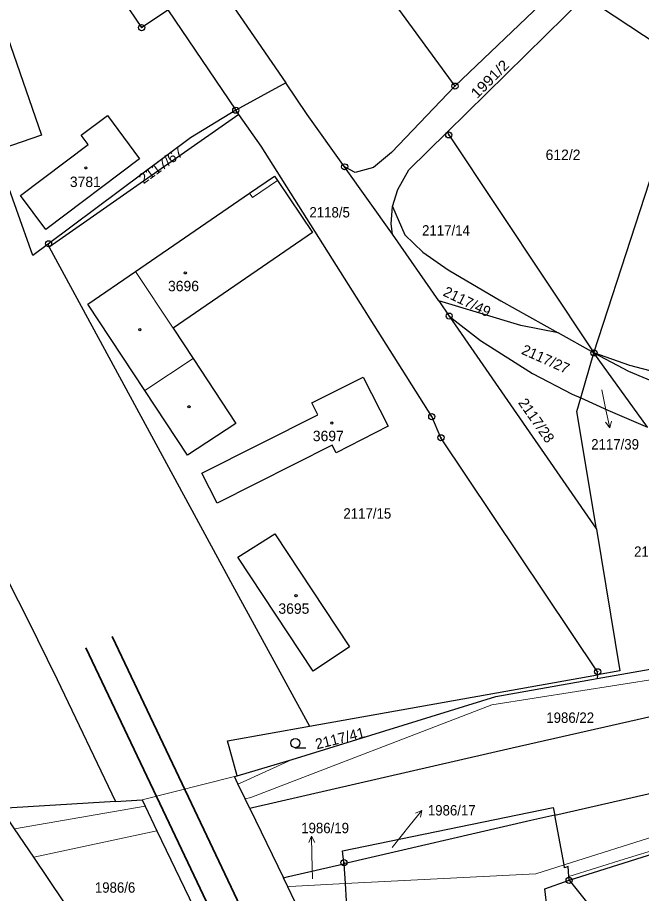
# Model space of a CAD drawing. Extents: x -679733 to -673243, y -1075091 to -1066557.
# Drawn here: x -675852.7 to -675750.8, y -1071520.5 to -1071377.5 of the extents above; entities that cross this region are included whole.
import ezdxf
from ezdxf.enums import TextEntityAlignment as Align

# ---------------------------------------------------------------- set-up
doc = ezdxf.new("R2010")
doc.units = 0
doc.header["$LTSCALE"] = 0.68
for name, color, linetype, lineweight in [('1', 7, 'Continuous', 25), ('3', 7, 'Continuous', 25), ('4', 7, 'Continuous', 13), ('5', 7, 'Continuous', 25), ('6', 7, 'Continuous', 35), ('7', 7, 'Continuous', 13), ('8', 7, 'Continuous', 25)]:
    doc.layers.add(name, color=color, linetype=linetype, lineweight=lineweight)
doc.layers.add('2', color=7, linetype='Continuous')

msp = doc.modelspace()

# ---------------------------------------------------------------- linework, layer by layer
at = {"layer": '1'}
for p, q in [((-675781.29, -1071388.68), (-675764, -1071372.14)), ((-675828.15, -1071376.24), (-675817.07, -1071392.61)), ((-675808.93, -1071388.15), (-675817.07, -1071392.61)), ((-675816.59, -1071393.3), (-675817.07, -1071392.61)), ((-675816.59, -1071393.3), (-675847.52, -1071414.95)), ((-675791.49, -1071412.85), (-675799.31, -1071401.85)), ((-675783.94, -1071423.72), (-675791.49, -1071412.85)), ((-675847.52, -1071414.95), (-675847.63, -1071414.41)), ((-675783.94, -1071423.72), (-675782.24, -1071426.22)), ((-675782.24, -1071426.22), (-675758.21, -1071461.03)), ((-675758.6, -1071432.23), (-675764.46, -1071428.95)), ((-675805.04, -1071493.15), (-675758.03, -1071484.77)), ((-675836.69, -1071505.46), (-675855.42, -1071506.6)), ((-675762.66, -1071518.33), (-675759.37, -1071522.39))]:
    msp.add_line(p, q, dxfattribs=at)
for points in [[(-675854.82, -1071284.95), (-675848.63, -1071294.37), (-675837.94, -1071309.28), (-675816.23, -1071340.27), (-675801.2, -1071361.46), (-675781.29, -1071388.68)], [(-675847.63, -1071414.41), (-675850.21, -1071416.33), (-675866.27, -1071371.22), (-675873.33, -1071374.74), (-675886.25, -1071340.1), (-675896.49, -1071301.05), (-675888.9, -1071295.99), (-675877.65, -1071312.62), (-675832.44, -1071379.13), (-675828.15, -1071376.24)], [(-675867.83, -1071302.12), (-675854.84, -1071321.36), (-675808.93, -1071388.15)], [(-675981.32, -1071321.28), (-675979.71, -1071320.17), (-675958.96, -1071344.08), (-675942.19, -1071358.69), (-675925.65, -1071376.26), (-675903.8, -1071399.59), (-675900.1, -1071402.8), (-675886.01, -1071422.07), (-675873.55, -1071440.05), (-675863.47, -1071455.5), (-675854.14, -1071469.73), (-675851.06, -1071475.72), (-675846.24, -1071485.53), (-675836.69, -1071505.46)], [(-675743.35, -1071385.17), (-675760.12, -1071374.06), (-675782.59, -1071396.19)], [(-675799.31, -1071401.85), (-675805.4, -1071393.29), (-675808.93, -1071388.15)], [(-675781.29, -1071388.68), (-675791.67, -1071399.52), (-675794.62, -1071401.98), (-675797.61, -1071402.8), (-675799.31, -1071401.85)], [(-675782.59, -1071396.19), (-675782.3, -1071396.64), (-675758.6, -1071432.23), (-675745.03, -1071390.44)], [(-675817.07, -1071392.61), (-675824.45, -1071397.14), (-675847.63, -1071414.41)], [(-675758.03, -1071484.77), (-675758.01, -1071484.29), (-675783.58, -1071446.08), (-675785.08, -1071442.63), (-675812.93, -1071398.49), (-675816.59, -1071393.3)], [(-675791.49, -1071408.32), (-675790.61, -1071405.53), (-675788.84, -1071402.35), (-675782.59, -1071396.19)], [(-675791.49, -1071412.85), (-675791.72, -1071411.17), (-675791.49, -1071408.32)], [(-675791.49, -1071408.32), (-675789.47, -1071412.94), (-675786.56, -1071415.8), (-675782.4, -1071418.64), (-675773.78, -1071423.73), (-675764.46, -1071428.95)], [(-675847.52, -1071414.95), (-675817.61, -1071470.14), (-675805.04, -1071493.15)], [(-675696.11, -1071420.65), (-675710.01, -1071445.5), (-675752.77, -1071434.27), (-675758.6, -1071432.23)], [(-675764.46, -1071428.95), (-675770.52, -1071427.75), (-675783.94, -1071423.72)], [(-675782.24, -1071426.22), (-675777.14, -1071430.21), (-675768.65, -1071435.57), (-675762.15, -1071438.95), (-675760.77, -1071439.57), (-675758.6, -1071432.23)], [(-675760.77, -1071439.57), (-675756.32, -1071441.58), (-675749.84, -1071444.33), (-675758.6, -1071432.23)], [(-675758.6, -1071432.23), (-675752.95, -1071435.22), (-675730.97, -1071444.42), (-675725.97, -1071446.45), (-675719.18, -1071448.79), (-675712.12, -1071450.99), (-675690.33, -1071455.9), (-675685.55, -1071451.33)], [(-675758.21, -1071461.03), (-675761.42, -1071441.77), (-675760.77, -1071439.57)], [(-675765.01, -1071507.69), (-675720.68, -1071497.6), (-675701.7, -1071493), (-675681.33, -1071488.01), (-675670.56, -1071485.93), (-675653.21, -1071481.97), (-675639.53, -1071478.73), (-675629.19, -1071475.57), (-675618.73, -1071471.91), (-675604.22, -1071466.89), (-675596.96, -1071465.22), (-675589.14, -1071463.42), (-675580.81, -1071461.62), (-675571.9, -1071459.71), (-675564.88, -1071458.18), (-675556.76, -1071456.48), (-675552.97, -1071456.9), (-675552.7, -1071457.95)], [(-675762.66, -1071518.33), (-675718.98, -1071504.52), (-675696.21, -1071498.47), (-675686.03, -1071495.76), (-675667.73, -1071490.69), (-675659.08, -1071487.52), (-675634.37, -1071480.95), (-675603.24, -1071472.27), (-675600.58, -1071471.53), (-675591.26, -1071468.63), (-675587.81, -1071467.56), (-675579.07, -1071464.85), (-675557.23, -1071459.13), (-675552.7, -1071457.95)], [(-675758.21, -1071461.03), (-675754.37, -1071484.11), (-675758.03, -1071484.77)], [(-675692.82, -1071478.48), (-675722.98, -1071485.64), (-675771.94, -1071496.74), (-675814.37, -1071506.52), (-675814.77, -1071506.62), (-675809.31, -1071517.91)], [(-675758.03, -1071484.77), (-675758.07, -1071485.41), (-675745.4, -1071483.17)], [(-675816.83, -1071501.25), (-675807.89, -1071498.61), (-675774.62, -1071488.33), (-675758.07, -1071485.41)], [(-675816.83, -1071501.25), (-675818.43, -1071495.54), (-675805.04, -1071493.15)], [(-675814.77, -1071506.62), (-675815.54, -1071505.04), (-675816.72, -1071502.59), (-675817.3, -1071501.39), (-675816.83, -1071501.25)], [(-675836.69, -1071505.46), (-675832.38, -1071505.2), (-675831.88, -1071506.24), (-675829.96, -1071510.26), (-675824.71, -1071521.21), (-675824.03, -1071522.63), (-675822.74, -1071525.31), (-675822, -1071526.86), (-675822.98, -1071527.31)], [(-675837.15, -1071533.74), (-675838.99, -1071531.01), (-675840.42, -1071528.88), (-675842.72, -1071525.48), (-675850.05, -1071514.58), (-675853.19, -1071509.92), (-675855.42, -1071506.6)], [(-675799.42, -1071515.63), (-675799.43, -1071515.45), (-675799.65, -1071513.5), (-675765.24, -1071506.45), (-675765.01, -1071507.69)], [(-675765.01, -1071507.69), (-675768.92, -1071508.58), (-675799.42, -1071515.63)], [(-675762.66, -1071518.33), (-675762.7, -1071517.7), (-675762.79, -1071516.09), (-675763.39, -1071516.29), (-675763.48, -1071515.8), (-675765.01, -1071507.69)], [(-675809.31, -1071517.91), (-675808.48, -1071517.73), (-675799.42, -1071515.63)], [(-675799.42, -1071515.63), (-675799.23, -1071518.87), (-675799.06, -1071521.66), (-675798.6, -1071523.24)], [(-675804.16, -1071523.03), (-675806.88, -1071522.93), (-675807.43, -1071521.79), (-675808.59, -1071519.4), (-675809.31, -1071517.91)], [(-675781.27, -1071526.04), (-675766.22, -1071523), (-675766.64, -1071519.74), (-675762.66, -1071518.33)]]:
    msp.add_lwpolyline(points, dxfattribs=at)
for points in [[(-675855.35, -1071377.62), (-675848.77, -1071396.69), (-675855.29, -1071398.93), (-675861.88, -1071379.88)], [(-675848.1, -1071412.06), (-675852.24, -1071406.55), (-675841.18, -1071398.21), (-675842.32, -1071396.7), (-675838, -1071393.46), (-675832.78, -1071400.55)], [(-675810.74, -1071403.35), (-675810.26, -1071404.06), (-675804.54, -1071412.58), (-675827.32, -1071428.17), (-675824.05, -1071433.13), (-675817.07, -1071443.74), (-675824.95, -1071448.94), (-675831.94, -1071438.34), (-675841.22, -1071424.28), (-675833.42, -1071418.93), (-675814.82, -1071406.15)], [(-675801.36, -1071447.28), (-675820.14, -1071456.75), (-675822.61, -1071451.86), (-675803.7, -1071442.32), (-675804.67, -1071440.38), (-675796.3, -1071436.17), (-675792.22, -1071444.17), (-675800.69, -1071448.57)], [(-675816.74, -1071465.56), (-675810.68, -1071461.78), (-675798.5, -1071480.23), (-675804.46, -1071484.17)]]:
    msp.add_lwpolyline(points, close=True, dxfattribs=at)
at = {"layer": '3'}
msp.add_line((-675807.363, -1071496.68), (-675805.613, -1071496.68), dxfattribs=at)
msp.add_circle((-675807.3629, -1071495.9298), 0.75, dxfattribs=at)
at = {"layer": '4'}
for p, q in [((-675814.34, -1071406.86), (-675810.26, -1071404.06)), ((-675814.82, -1071406.15), (-675814.34, -1071406.86)), ((-675827.32, -1071428.17), (-675833.42, -1071418.93)), ((-675831.94, -1071438.34), (-675824.05, -1071433.13)), ((-675775.26, -1071489.68), (-675723.75, -1071481.57)), ((-675814.63, -1071504.8), (-675775.26, -1071489.68)), ((-675816.45, -1071502.52), (-675807.89, -1071498.61)), ((-675832.38, -1071505.2), (-675817.3, -1071501.39)), ((-675816.72, -1071502.59), (-675816.45, -1071502.52)), ((-675763.48, -1071515.8), (-675719.73, -1071501.99)), ((-675717.48, -1071503.73), (-675753.65, -1071514.87)), ((-675815.54, -1071505.04), (-675814.63, -1071504.8)), ((-675853.19, -1071509.92), (-675831.88, -1071506.24)), ((-675850.05, -1071514.58), (-675829.96, -1071510.26)), ((-675753.65, -1071514.87), (-675762.7, -1071517.7)), ((-675768.11, -1071517.26), (-675763.48, -1071515.8)), ((-675799.23, -1071518.87), (-675768.11, -1071517.26)), ((-675808.23, -1071519.33), (-675808.59, -1071519.4)), ((-675808.23, -1071519.33), (-675799.23, -1071518.87))]:
    msp.add_line(p, q, dxfattribs=at)
at = {"layer": '5'}
for centre in [(-675841.5568, -1071402.0292), (-675825.3168, -1071419.1692), (-675832.7268, -1071428.4392), (-675824.7168, -1071441.0192), (-675801.3968, -1071443.6792), (-675807.2368, -1071471.8592)]:
    msp.add_circle(centre, 0.175, dxfattribs=at)
at = {"layer": '6'}
for p, q in [((-675824.81, -1071504.74), (-675837.24, -1071478.53)), ((-675829.46, -1071505.81), (-675841.54, -1071480.37)), ((-675824.81, -1071504.74), (-675815.86, -1071523.61)), ((-675829.46, -1071505.81), (-675820.49, -1071524.71))]:
    msp.add_line(p, q, dxfattribs=at)
at = {"layer": '7'}
for p, q in [((-675756.016, -1071444.435), (-675755.734, -1071443.352)), ((-675786.701, -1071506.918), (-675787.721, -1071507.381)), ((-675804.692, -1071511.139), (-675805.176, -1071512.15))]:
    msp.add_line(p, q, dxfattribs=at)
for points in [[(-675757.32, -1071438.24), (-675756.64, -1071441.5), (-675756.016, -1071444.435), (-675756.714, -1071443.56)], [(-675791.54, -1071512.95), (-675788.59, -1071509.25), (-675786.701, -1071506.918), (-675786.943, -1071508.011)], [(-675804.57, -1071518.1), (-675804.64, -1071514.14), (-675804.692, -1071511.139), (-675804.174, -1071512.132)]]:
    msp.add_lwpolyline(points, dxfattribs=at)
at = {"layer": '8'}
for centre, radius in [((-675832.44, -1071379.1299), 0.5), ((-675832.44, -1071379.1299), 0.0303), ((-675781.29, -1071388.6799), 0.5), ((-675781.29, -1071388.6799), 0.0303), ((-675817.07, -1071392.6099), 0.5), ((-675817.07, -1071392.6099), 0.0303), ((-675782.3, -1071396.6399), 0.5), ((-675782.3, -1071396.6399), 0.0303), ((-675799.31, -1071401.8499), 0.5), ((-675799.31, -1071401.8499), 0.0303), ((-675847.63, -1071414.4099), 0.5), ((-675847.63, -1071414.4099), 0.0303), ((-675782.24, -1071426.2199), 0.5), ((-675782.24, -1071426.2199), 0.0303), ((-675758.6, -1071432.2299), 0.5), ((-675758.6, -1071432.2299), 0.0303), ((-675785.08, -1071442.6299), 0.5), ((-675785.08, -1071442.6299), 0.0303), ((-675783.58, -1071446.0799), 0.5), ((-675783.58, -1071446.0799), 0.0303), ((-675758.01, -1071484.2899), 0.5), ((-675758.01, -1071484.2899), 0.0303), ((-675799.43, -1071515.4499), 0.5), ((-675799.43, -1071515.4499), 0.0303), ((-675762.66, -1071518.3299), 0.5), ((-675762.66, -1071518.3299), 0.0303)]:
    msp.add_circle(centre, radius, dxfattribs=at)

# ---------------------------------------------------------------- texts
at = {"layer": '2', "width": 1.1}
msp.add_text('1991/2', height=1.7, rotation=45, dxfattribs=at).set_placement((-675774.9875, -1071388.1195), align=Align.CENTER)
at = {"layer": '2'}
msp.add_text('2117/67', height=1.7, rotation=36, dxfattribs=at).set_placement((-675832.13, -1071404.717))
for s, p in [('612/2', (-675763.65, -1071400.739)), ('3696', (-675825.61, -1071422.16)), ('3697', (-675801.97, -1071446.64)), ('3695', (-675807.59, -1071474.82))]:
    msp.add_text(s, height=1.7, dxfattribs=at).set_placement(p, align=Align.CENTER)
msp.add_text('3781', height=1.7, dxfattribs=at).set_placement((-675844.16, -1071405.15))
at = {"layer": '2', "width": 0.95}
for s, p in [('2118/5', (-675805.05, -1071410.12)), ('2117/39', (-675759.06, -1071448.003)), ('1986/22', (-675766.39, -1071492.63)), ('1986/17', (-675785.72, -1071507.749))]:
    msp.add_text(s, height=1.7, dxfattribs=at).set_placement(p)
for s, p in [('2117/14', (-675782.76, -1071413.08)), ('2117/15', (-675795.6, -1071459.29)), ('2117/40', (-675748.15, -1071465.519)), ('1986/6', (-675836.779, -1071520.36))]:
    msp.add_text(s, height=1.7, dxfattribs=at).set_placement(p, align=Align.CENTER)
at = {"layer": '2'}
for s, rotation, p in [('2117/49', 334, (-675779.6841, -1071424.6146)), ('2117/27', 336, (-675766.8252, -1071434.0087)), ('2117/28', 305, (-675768.6877, -1071443.7425)), ('2117/41', 14, (-675799.8566, -1071495.9703))]:
    msp.add_text(s, height=1.7, rotation=rotation, dxfattribs=at).set_placement(p, align=Align.CENTER)
at = {"layer": '2', "width": 0.95}
msp.add_text('1986/19', height=1.7, dxfattribs=at).set_placement((-675798.59, -1071510.64), align=Align.RIGHT)

doc.saveas('drawing.dxf')
